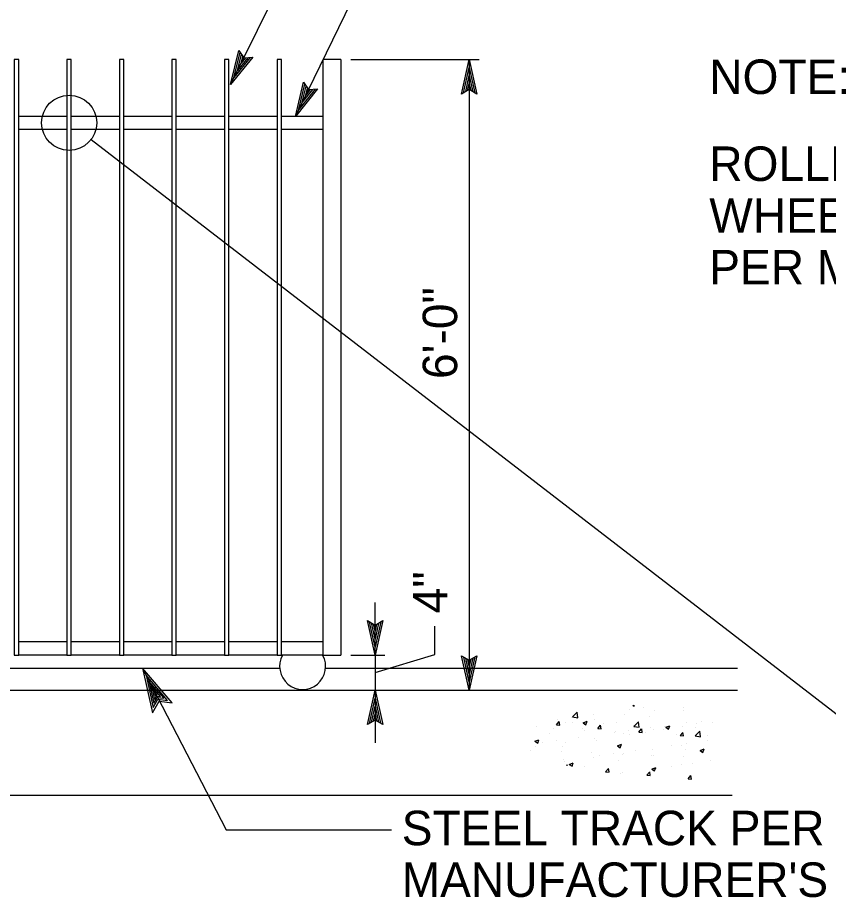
# Model space of a CAD drawing. Extents: x 6710407 to 6714861, y 1868090 to 1871317.
# Drawn here: x 6711663.5 to 6711804.5, y 1869297.2 to 1869450.3 of the extents above; entities that cross this region are included whole.
import ezdxf

# ---------------------------------------------------------------- set-up
doc = ezdxf.new("R2010")
doc.units = 0
for name, color, linetype in [('Erosion C (Lv35)', 7, 'Continuous'), ('G-MARK', 7, 'Continuous'), ('G-TEXT', 7, 'Continuous'), ('Misc CnstDet(22)', 7, 'Continuous'), ('Nongeo Data(60)', 7, 'Continuous')]:
    doc.layers.add(name, color=color, linetype=linetype)

# ---------------------------------------------------------------- blocks, each defined once
blk = doc.blocks.new('SC8415')
at = {"layer": 'Erosion C (Lv35)'}
for p, q in [((-1.69662, 1.7688), (-1.69662, 1.7688)), ((-1.69606, 1.76963), (-1.69579, 1.76945)), ((-1.69579, 1.76945), (-1.69573, 1.76963)), ((-1.69408, 1.76913), (-1.69408, 1.76913)), ((-1.69228, 1.76861), (-1.69228, 1.76861)), ((-1.68716, 1.76862), (-1.68716, 1.76862)), ((-1.68715, 1.76926), (-1.68715, 1.76926)), ((-1.70943, 1.76711), (-1.70943, 1.76711)), ((-1.70689, 1.76745), (-1.70689, 1.76745)), ((-1.70669, 1.76754), (-1.7059, 1.76836)), ((-1.70669, 1.76754), (-1.70579, 1.7674)), ((-1.70579, 1.7674), (-1.7059, 1.76836)), ((-1.70304, 1.76795), (-1.70304, 1.76795)), ((-1.70278, 1.76714), (-1.70278, 1.76714)), ((-1.6975, 1.7679), (-1.6975, 1.7679)), ((-1.69309, 1.7676), (-1.69309, 1.7676)), ((-1.71312, 1.76577), (-1.71312, 1.76577)), ((-1.70955, 1.76614), (-1.70906, 1.76672)), ((-1.70955, 1.76614), (-1.70894, 1.76608)), ((-1.70894, 1.76609), (-1.70906, 1.76672)), ((-1.70791, 1.76649), (-1.70791, 1.76649)), ((-1.70672, 1.76656), (-1.70672, 1.76656)), ((-1.70494, 1.76557), (-1.70494, 1.76557)), ((-1.70484, 1.76651), (-1.70412, 1.76679)), ((-1.70484, 1.76651), (-1.70433, 1.76617)), ((-1.70433, 1.76617), (-1.70412, 1.76679)), ((-1.70226, 1.7655), (-1.70177, 1.76608)), ((-1.70226, 1.7655), (-1.70165, 1.76545)), ((-1.70165, 1.76545), (-1.70177, 1.76609)), ((-1.7013, 1.76633), (-1.7013, 1.76633)), ((-1.69901, 1.76659), (-1.69901, 1.76659)), ((-1.69588, 1.7661), (-1.69588, 1.7661)), ((-1.69585, 1.76586), (-1.69506, 1.76668)), ((-1.69585, 1.76586), (-1.69494, 1.76572)), ((-1.69494, 1.76572), (-1.69506, 1.76668)), ((-1.6929, 1.76563), (-1.6929, 1.76563)), ((-1.69045, 1.76587), (-1.69045, 1.76587)), ((-1.69023, 1.7657), (-1.68952, 1.76597)), ((-1.69023, 1.7657), (-1.68973, 1.76536)), ((-1.68973, 1.76536), (-1.68952, 1.76597)), ((-1.68727, 1.76588), (-1.68727, 1.76588)), ((-1.68649, 1.76648), (-1.68649, 1.76648)), ((-1.68503, 1.76565), (-1.68503, 1.76565)), ((-1.68473, 1.76639), (-1.68473, 1.76639)), ((-1.68394, 1.76681), (-1.68394, 1.76681)), ((-1.682, 1.76664), (-1.682, 1.76664)), ((-1.71086, 1.76455), (-1.71086, 1.76455)), ((-1.71, 1.76543), (-1.71, 1.76543)), ((-1.70571, 1.76395), (-1.70571, 1.76395)), ((-1.70458, 1.7652), (-1.70458, 1.7652)), ((-1.6993, 1.76479), (-1.6993, 1.76479)), ((-1.69916, 1.76497), (-1.69916, 1.76497)), ((-1.69762, 1.76452), (-1.69762, 1.76452)), ((-1.69675, 1.76513), (-1.69675, 1.76513)), ((-1.69658, 1.76435), (-1.69658, 1.76435)), ((-1.69497, 1.76486), (-1.69449, 1.76545)), ((-1.69497, 1.76486), (-1.69437, 1.76481)), ((-1.69437, 1.76481), (-1.69448, 1.76545)), ((-1.69373, 1.76474), (-1.69373, 1.76474)), ((-1.69241, 1.76523), (-1.69241, 1.76523)), ((-1.69065, 1.76537), (-1.69065, 1.76537)), ((-1.68831, 1.76451), (-1.68831, 1.76451)), ((-1.68769, 1.76423), (-1.6872, 1.76481)), ((-1.68769, 1.76423), (-1.68708, 1.76417)), ((-1.68708, 1.76417), (-1.6872, 1.76481)), ((-1.685, 1.76418), (-1.68421, 1.765)), ((-1.685, 1.76418), (-1.6841, 1.76404)), ((-1.6841, 1.76404), (-1.68421, 1.765)), ((-1.68289, 1.76428), (-1.68289, 1.76428)), ((-1.71337, 1.76324), (-1.71266, 1.76351)), ((-1.71337, 1.76324), (-1.71287, 1.7629)), ((-1.71325, 1.76239), (-1.71325, 1.76239)), ((-1.71287, 1.7629), (-1.71266, 1.76351)), ((-1.7121, 1.7631), (-1.7121, 1.7631)), ((-1.70956, 1.76344), (-1.70956, 1.76344)), ((-1.70803, 1.7631), (-1.70803, 1.7631)), ((-1.7029, 1.76375), (-1.7029, 1.76375)), ((-1.7025, 1.76334), (-1.7025, 1.76334)), ((-1.69877, 1.76242), (-1.69806, 1.7627)), ((-1.69877, 1.76242), (-1.69827, 1.76208)), ((-1.69826, 1.76208), (-1.69806, 1.7627)), ((-1.68916, 1.76247), (-1.68916, 1.76247)), ((-1.6874, 1.7625), (-1.6874, 1.7625)), ((-1.68662, 1.7628), (-1.68662, 1.7628)), ((-1.68277, 1.76331), (-1.68277, 1.76331)), ((-1.71417, 1.76163), (-1.71417, 1.76163)), ((-1.70874, 1.7614), (-1.70874, 1.7614)), ((-1.70843, 1.76232), (-1.70843, 1.76232)), ((-1.70332, 1.76117), (-1.70332, 1.76117)), ((-1.69943, 1.76112), (-1.69943, 1.76112)), ((-1.6979, 1.76094), (-1.6979, 1.76094)), ((-1.69775, 1.76113), (-1.69775, 1.76113)), ((-1.69558, 1.76162), (-1.69558, 1.76162)), ((-1.69253, 1.76185), (-1.69253, 1.76185)), ((-1.68677, 1.76182), (-1.68677, 1.76182)), ((-1.68417, 1.76161), (-1.68346, 1.76188)), ((-1.68417, 1.76161), (-1.68366, 1.76127)), ((-1.68366, 1.76127), (-1.68346, 1.76188)), ((-1.70839, 1.75994), (-1.70839, 1.75994)), ((-1.70815, 1.75972), (-1.70815, 1.75972)), ((-1.70731, 1.75915), (-1.7066, 1.75942)), ((-1.7068, 1.75881), (-1.7066, 1.75942)), ((-1.70302, 1.76037), (-1.70302, 1.76037)), ((-1.70197, 1.76078), (-1.70197, 1.76078)), ((-1.69862, 1.75978), (-1.69862, 1.75978)), ((-1.6927, 1.7608), (-1.6927, 1.7608)), ((-1.69247, 1.76071), (-1.69247, 1.76071)), ((-1.68705, 1.76048), (-1.68705, 1.76048)), ((-1.68544, 1.7593), (-1.68544, 1.7593)), ((-1.68224, 1.75988), (-1.68224, 1.75988)), ((-1.70775, 1.75896), (-1.70765, 1.75908)), ((-1.70762, 1.7589), (-1.70765, 1.75908)), ((-1.70731, 1.75915), (-1.7068, 1.75881)), ((-1.70455, 1.75876), (-1.70455, 1.75876)), ((-1.70085, 1.75786), (-1.70036, 1.75844)), ((-1.70085, 1.75786), (-1.70025, 1.7578)), ((-1.70024, 1.75781), (-1.70036, 1.75844)), ((-1.69787, 1.75775), (-1.69787, 1.75775)), ((-1.69357, 1.75722), (-1.69308, 1.7578)), ((-1.69296, 1.75717), (-1.69307, 1.75781)), ((-1.69271, 1.75833), (-1.692, 1.75861)), ((-1.69271, 1.75833), (-1.6922, 1.75799)), ((-1.69265, 1.75847), (-1.69265, 1.75847)), ((-1.6922, 1.75799), (-1.69199, 1.75861)), ((-1.69183, 1.75846), (-1.69183, 1.75846)), ((-1.68929, 1.7588), (-1.68929, 1.7588)), ((-1.68752, 1.75912), (-1.68752, 1.75912)), ((-1.69825, 1.75762), (-1.69825, 1.75762)), ((-1.69357, 1.75722), (-1.69296, 1.75717)), ((-1.68628, 1.75658), (-1.68579, 1.75717)), ((-1.68628, 1.75658), (-1.68567, 1.75653)), ((-1.68567, 1.75653), (-1.68579, 1.75717))]:
    blk.add_line(p, q, dxfattribs=at)

msp = doc.modelspace()

# ---------------------------------------------------------------- linework, layer by layer
at = {"layer": 'G-MARK'}
for p, q in [((6711721.42, 1869443.04), (6711743.77, 1869443.04)), ((6711742.05, 1869443.04), (6711742.05, 1869333.31)), ((6711676.24, 1869429.11), (6711840.03, 1869302.87)), ((6711725.66, 1869339.41), (6711725.66, 1869348.55)), ((6711736.07, 1869339.49), (6711736.07, 1869344.46)), ((6711721.42, 1869339.41), (6711727.37, 1869339.41)), ((6711725.66, 1869336.36), (6711736.07, 1869339.49)), ((6711725.66, 1869339.41), (6711725.66, 1869333.31)), ((6711685.2, 1869337.14), (6711699.74, 1869309.03)), ((6711725.66, 1869333.31), (6711725.66, 1869324.17)), ((6711699.74, 1869309.03), (6711728.5, 1869309.03))]:
    msp.add_line(p, q, dxfattribs=at)
for points in [[(6711700.49, 1869438.68), (6711742.67, 1869523.6), (6711742.67, 1869523.6)], [(6711711.79, 1869433.14), (6711739.89, 1869490.86), (6711739.89, 1869490.86)]]:
    msp.add_lwpolyline(points, dxfattribs=at)
at = {"layer": 'G-TEXT'}
for p, q in [((6711740.71, 1869437.04), (6711742.05, 1869443.04)), ((6711742.05, 1869443.04), (6711742.05, 1869443.04)), ((6711742.05, 1869443.04), (6711743.38, 1869437.04)), ((6711741.07, 1869437.26), (6711742.05, 1869441.66)), ((6711741.43, 1869437.49), (6711742.05, 1869440.28)), ((6711742.05, 1869440.28), (6711742.68, 1869437.45)), ((6711742.06, 1869441.65), (6711743.02, 1869437.28)), ((6711741.77, 1869437.67), (6711742.05, 1869438.9)), ((6711742.05, 1869438.9), (6711742.32, 1869437.69)), ((6711742.05, 1869437.84), (6711740.71, 1869437.04)), ((6711743.38, 1869437.04), (6711742.05, 1869437.84)), ((6711740.71, 1869437.04), (6711740.71, 1869437.04)), ((6711743.38, 1869437.04), (6711743.38, 1869437.04)), ((6711725.66, 1869339.41), (6711724.33, 1869345.41)), ((6711724.33, 1869345.41), (6711724.33, 1869345.41)), ((6711724.33, 1869345.41), (6711725.66, 1869344.61)), ((6711725.66, 1869344.61), (6711727, 1869345.41)), ((6711727, 1869345.41), (6711725.66, 1869339.41)), ((6711727, 1869345.41), (6711727, 1869345.41)), ((6711725.65, 1869340.8), (6711724.69, 1869345.17)), ((6711725.66, 1869342.17), (6711725.03, 1869345)), ((6711725.66, 1869343.55), (6711725.39, 1869344.76)), ((6711726.64, 1869345.19), (6711725.66, 1869340.79)), ((6711726.28, 1869344.96), (6711725.66, 1869342.17)), ((6711725.93, 1869344.78), (6711725.66, 1869343.55)), ((6711725.66, 1869339.41), (6711725.66, 1869339.41)), ((6711742.05, 1869333.31), (6711740.72, 1869339.31)), ((6711740.72, 1869339.31), (6711740.72, 1869339.31)), ((6711740.72, 1869339.31), (6711742.05, 1869338.51)), ((6711742.05, 1869338.51), (6711743.39, 1869339.31)), ((6711743.39, 1869339.31), (6711742.05, 1869333.31)), ((6711743.39, 1869339.31), (6711743.39, 1869339.31)), ((6711742.05, 1869334.7), (6711741.08, 1869339.08)), ((6711742.05, 1869336.08), (6711741.43, 1869338.9)), ((6711742.05, 1869337.46), (6711741.79, 1869338.67)), ((6711743.04, 1869339.1), (6711742.05, 1869334.69)), ((6711742.68, 1869338.86), (6711742.05, 1869336.08)), ((6711742.33, 1869338.69), (6711742.05, 1869337.46)), ((6711724.32, 1869327.31), (6711725.66, 1869333.31)), ((6711725.66, 1869333.31), (6711725.66, 1869333.31)), ((6711725.66, 1869333.31), (6711726.99, 1869327.31)), ((6711742.05, 1869333.31), (6711742.05, 1869333.31)), ((6711724.67, 1869327.53), (6711725.66, 1869331.93)), ((6711725.66, 1869331.92), (6711726.63, 1869327.55)), ((6711725.03, 1869327.76), (6711725.65, 1869330.55)), ((6711725.65, 1869330.55), (6711726.28, 1869327.73)), ((6711725.38, 1869327.94), (6711725.65, 1869329.17)), ((6711725.65, 1869329.17), (6711725.92, 1869327.96)), ((6711725.66, 1869328.11), (6711724.32, 1869327.31)), ((6711724.32, 1869327.31), (6711724.32, 1869327.31)), ((6711726.99, 1869327.31), (6711725.66, 1869328.11)), ((6711726.99, 1869327.31), (6711726.99, 1869327.31))]:
    msp.add_line(p, q, dxfattribs=at)
for points in [[(6711685.2, 1869337.14), (6711686.92, 1869329.37), (6711688.07, 1869331.38), (6711690.37, 1869331.09), (6711685.2, 1869337.14)], [(6711685.81, 1869335.91), (6711687.05, 1869330.28), (6711687.89, 1869331.74), (6711689.56, 1869331.53), (6711685.81, 1869335.91)], [(6711686.32, 1869334.88), (6711687.17, 1869331.05), (6711687.74, 1869332.04), (6711688.88, 1869331.9), (6711686.32, 1869334.88)], [(6711686.99, 1869334.09), (6711687.37, 1869332.35), (6711687.49, 1869332.55), (6711687.72, 1869332.52), (6711686.56, 1869333.88)], [(6711686.75, 1869334.04), (6711687.26, 1869331.67), (6711687.62, 1869332.28), (6711688.33, 1869332.2), (6711686.75, 1869334.04)]]:
    msp.add_lwpolyline(points, dxfattribs=at)
at = {"layer": 'Misc CnstDet(22)'}
msp.add_circle((6711672.43, 1869432.04), 4.8, dxfattribs=at)
at = {"layer": 'Nongeo Data(60)'}
for p, q in [((6711700.49, 1869438.68), (6711701.98, 1869444.64)), ((6711704.37, 1869443.45), (6711700.49, 1869438.68)), ((6711701.11, 1869439.92), (6711702.19, 1869444.27)), ((6711703.95, 1869443.42), (6711701.11, 1869439.91)), ((6711701.73, 1869441.15), (6711702.43, 1869443.96)), ((6711703.53, 1869443.37), (6711701.73, 1869441.15)), ((6711701.98, 1869444.64), (6711701.98, 1869444.64)), ((6711701.98, 1869444.64), (6711702.81, 1869443.33)), ((6711702.34, 1869442.39), (6711702.64, 1869443.59)), ((6711703.14, 1869443.36), (6711702.34, 1869442.39)), ((6711702.81, 1869443.33), (6711704.37, 1869443.45)), ((6711704.37, 1869443.45), (6711704.37, 1869443.45)), ((6711719.71, 1869443.04), (6711716.56, 1869443.04)), ((6711716.56, 1869443.04), (6711716.56, 1869383.61)), ((6711719.71, 1869443.04), (6711719.71, 1869383.61)), ((6711711.79, 1869433.14), (6711713.22, 1869439.11)), ((6711712.4, 1869434.39), (6711713.44, 1869438.74)), ((6711713.22, 1869439.11), (6711713.22, 1869439.11)), ((6711713.22, 1869439.11), (6711714.07, 1869437.81)), ((6711700.49, 1869438.68), (6711700.49, 1869438.68)), ((6711715.62, 1869437.94), (6711711.79, 1869433.14)), ((6711715.21, 1869437.9), (6711712.4, 1869434.38)), ((6711713, 1869435.62), (6711713.68, 1869438.43)), ((6711714.78, 1869437.85), (6711713, 1869435.62)), ((6711713.61, 1869436.86), (6711713.9, 1869438.06)), ((6711714.39, 1869437.84), (6711713.61, 1869436.86)), ((6711714.07, 1869437.81), (6711715.62, 1869437.94)), ((6711715.62, 1869437.94), (6711715.62, 1869437.94)), ((6711672.03, 1869433.14), (6711663.65, 1869433.14)), ((6711681.18, 1869433.14), (6711672.8, 1869433.14)), ((6711690.32, 1869433.14), (6711681.94, 1869433.14)), ((6711699.47, 1869433.14), (6711691.08, 1869433.14)), ((6711708.61, 1869433.14), (6711700.23, 1869433.14)), ((6711716.56, 1869433.14), (6711709.37, 1869433.14)), ((6711711.79, 1869433.14), (6711711.79, 1869433.14)), ((6711672.03, 1869430.85), (6711663.65, 1869430.85)), ((6711681.18, 1869430.85), (6711672.8, 1869430.85)), ((6711690.32, 1869430.85), (6711681.94, 1869430.85)), ((6711699.47, 1869430.85), (6711691.08, 1869430.85)), ((6711708.61, 1869430.85), (6711700.23, 1869430.85)), ((6711716.56, 1869430.85), (6711709.37, 1869430.85)), ((6711719.71, 1869383.61), (6711719.71, 1869339.41)), ((6711672.03, 1869341.7), (6711663.65, 1869341.7)), ((6711681.18, 1869341.7), (6711672.8, 1869341.7)), ((6711690.32, 1869341.7), (6711681.94, 1869341.7)), ((6711699.47, 1869341.7), (6711691.08, 1869341.7)), ((6711708.61, 1869341.7), (6711700.23, 1869341.7)), ((6711716.56, 1869341.7), (6711709.37, 1869341.7)), ((6711672.03, 1869339.41), (6711663.65, 1869339.41)), ((6711681.18, 1869339.41), (6711672.8, 1869339.41)), ((6711690.32, 1869339.41), (6711681.94, 1869339.41)), ((6711699.47, 1869339.41), (6711691.08, 1869339.41)), ((6711708.61, 1869339.41), (6711700.23, 1869339.41)), ((6711716.56, 1869339.41), (6711709.37, 1869339.41)), ((6711716.56, 1869339.41), (6711719.71, 1869339.41)), ((6711617.59, 1869337.14), (6711709.07, 1869337.14)), ((6711717.05, 1869337.14), (6711788.71, 1869337.14)), ((6711551.08, 1869333.31), (6711788.71, 1869333.31)), ((6711721.42, 1869333.31), (6711743.77, 1869333.31)), ((6711721.42, 1869333.31), (6711727.37, 1869333.31)), ((6711725.66, 1869333.31), (6711725.66, 1869333.31)), ((6711742.05, 1869333.31), (6711742.05, 1869333.31)), ((6711623.21, 1869315.03), (6711787.8, 1869315.03))]:
    msp.add_line(p, q, dxfattribs=at)
for points in [[(6711662.89, 1869339.41), (6711663.65, 1869339.41), (6711663.65, 1869443.04), (6711662.89, 1869443.04)], [(6711672.03, 1869339.41), (6711672.8, 1869339.41), (6711672.8, 1869443.04), (6711672.03, 1869443.04)], [(6711681.18, 1869339.41), (6711681.94, 1869339.41), (6711681.94, 1869443.04), (6711681.18, 1869443.04)], [(6711690.32, 1869339.41), (6711691.08, 1869339.41), (6711691.08, 1869443.04), (6711690.32, 1869443.04)], [(6711699.47, 1869339.41), (6711700.23, 1869339.41), (6711700.23, 1869443.04), (6711699.47, 1869443.04)], [(6711708.61, 1869339.41), (6711709.37, 1869339.41), (6711709.37, 1869443.04), (6711708.61, 1869443.04)]]:
    msp.add_lwpolyline(points, close=True, dxfattribs=at)
msp.add_lwpolyline([(6711716.56, 1869383.61), (6711716.56, 1869339.41)], dxfattribs=at)
msp.add_arc((6711713.06, 1869337.44), 4, 150.5121, 29.4879, dxfattribs=at)

# ---------------------------------------------------------------- block references
at = {"layer": 'Nongeo Data(60)', "xscale": 984.251968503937, "yscale": 984.251968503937}
msp.add_blockref('SC8415', (6713439.85, 1867588.95), dxfattribs=at)

# ---------------------------------------------------------------- texts
at = {"layer": 'Nongeo Data(60)'}
for s, p in [('NOTE:', (6711783.81, 1869437.05)), ('ROLLING STL FENCE GATE,', (6711783.81, 1869421.92)), ('WHEELS, TRACK AND MOTOR', (6711783.81, 1869412.92)), ('PER MANUFACTURER', (6711783.81, 1869403.92)), ('STEEL TRACK PER ', (6711730.3, 1869306.33)), ("MANUFACTURER'S", (6711730.3, 1869297.33))]:
    msp.add_text(s, height=6, dxfattribs=at).set_placement(p)
for s, p in [('6\'-0"', (6711739.95, 1869387.46)), ('4"', (6711738.26, 1869346.68))]:
    msp.add_text(s, height=6, rotation=90, dxfattribs=at).set_placement(p)

doc.saveas('drawing.dxf')
